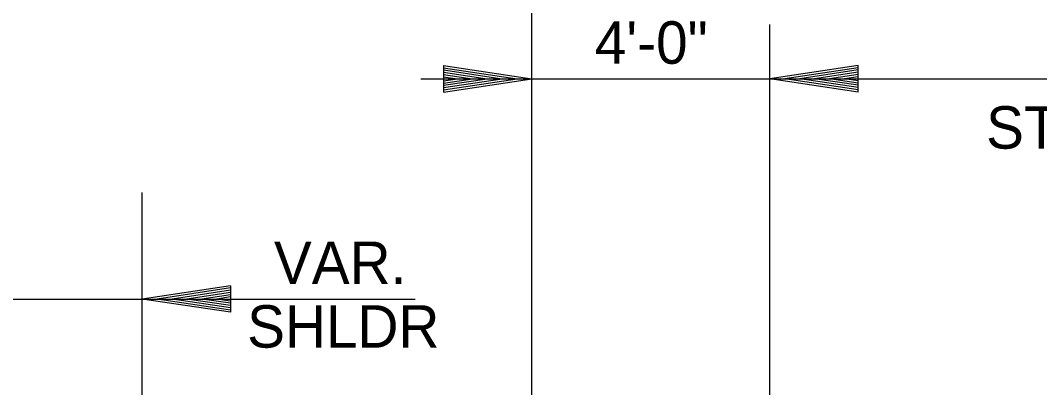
# Model space of a CAD drawing. Extents: x 1807779 to 1818251, y 673292 to 678849.
# Drawn here: x 1813400.8 to 1813573.8, y 678688.5 to 678750.8 of the extents above; entities that cross this region are included whole.
import ezdxf

# ---------------------------------------------------------------- set-up
doc = ezdxf.new("R2010")
doc.units = 0
doc.layers.add('Dimensions', color=7, linetype='Continuous')

msp = doc.modelspace()

# ---------------------------------------------------------------- linework, layer by layer
at = {"layer": 'Dimensions'}
for p, q in [((1813487.67, 678608.69), (1813487.67, 678825.67)), ((1813528.05, 678608.69), (1813528.05, 678750.09)), ((1813472.67, 678743.12), (1813487.67, 678740.87)), ((1813472.67, 678743.12), (1813472.67, 678738.62)), ((1813472.67, 678742.75), (1813485.17, 678740.87)), ((1813472.67, 678742.37), (1813482.59, 678740.87)), ((1813472.67, 678741.99), (1813480.09, 678740.87)), ((1813543.05, 678743.12), (1813528.05, 678740.87)), ((1813543.05, 678742.75), (1813530.56, 678740.87)), ((1813543.05, 678742.37), (1813533.14, 678740.87)), ((1813543.05, 678741.99), (1813535.64, 678740.87)), ((1813543.05, 678738.62), (1813543.05, 678743.12)), ((1813468.81, 678740.87), (1813528.05, 678740.87)), ((1813472.67, 678741.6), (1813477.55, 678740.87)), ((1813472.67, 678741.23), (1813475.04, 678740.87)), ((1813472.67, 678738.62), (1813487.67, 678740.87)), ((1813472.67, 678740.14), (1813477.55, 678740.87)), ((1813472.67, 678739.38), (1813482.59, 678740.87)), ((1813472.67, 678739), (1813485.17, 678740.87)), ((1813472.67, 678739.76), (1813480.09, 678740.87)), ((1813472.67, 678740.52), (1813475.04, 678740.87)), ((1813528.05, 678740.87), (1813678.05, 678740.87)), ((1813543.05, 678738.62), (1813528.05, 678740.87)), ((1813543.05, 678739), (1813530.56, 678740.87)), ((1813543.05, 678739.38), (1813533.14, 678740.87)), ((1813543.05, 678739.76), (1813535.64, 678740.87)), ((1813543.05, 678741.61), (1813538.18, 678740.87)), ((1813543.05, 678740.15), (1813538.18, 678740.87)), ((1813543.05, 678741.23), (1813540.68, 678740.87)), ((1813543.05, 678740.52), (1813540.68, 678740.87)), ((1813421.53, 678604.08), (1813421.53, 678721.56)), ((1813436.53, 678705.76), (1813421.53, 678703.51)), ((1813436.53, 678705.76), (1813436.53, 678701.26)), ((1813436.53, 678705.39), (1813424.04, 678703.51)), ((1813436.53, 678705), (1813426.62, 678703.51)), ((1813436.53, 678704.63), (1813429.11, 678703.51)), ((1813436.53, 678704.24), (1813431.66, 678703.51)), ((1813436.53, 678703.86), (1813434.16, 678703.51)), ((1813286.49, 678703.51), (1813467.83, 678703.51)), ((1813436.53, 678701.26), (1813421.53, 678703.51)), ((1813436.53, 678701.64), (1813424.04, 678703.51)), ((1813436.53, 678702.02), (1813426.62, 678703.51)), ((1813436.53, 678702.39), (1813429.11, 678703.51)), ((1813436.53, 678702.78), (1813431.66, 678703.51)), ((1813436.53, 678703.16), (1813434.16, 678703.51))]:
    msp.add_line(p, q, dxfattribs=at)

# ---------------------------------------------------------------- texts
for s, p in [('4\'-0"', (1813498.33, 678743.42)), ('STAGE 2 TRAFFIC', (1813564.74, 678729.02)), ('VAR.', (1813443.88, 678706.06)), ('SHLDR', (1813439.33, 678695.26))]:
    msp.add_text(s, height=7.2, dxfattribs=at).set_placement(p)

doc.saveas('drawing.dxf')
